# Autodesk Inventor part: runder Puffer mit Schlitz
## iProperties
Created: 2009-03
Part Number: runder Puffer mit Schlitz
Document SubType Name: Modeling
Designer: Hans-Jürgen Eicke
Author: Hans-Jürgen Eicke
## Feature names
1. Extrusion1
2. Extrusion2
3. Extrusion3
4. Extrusion4
5. Extrusion5
6. Extrusion6
7. Extrusion8
8. Rundung1 [Fillet]
9. Drehung2 [Revolution]
10. Extrusion10
11. Extrusion11
12. Extrusion12
13. Extrusion13
14. Extrusion14
15. Extrusion15
16. Rundung2 [Fillet]
17. Extrusion16
18. Rundung3 [Fillet]
19. Extrusion17
20. Extrusion18
